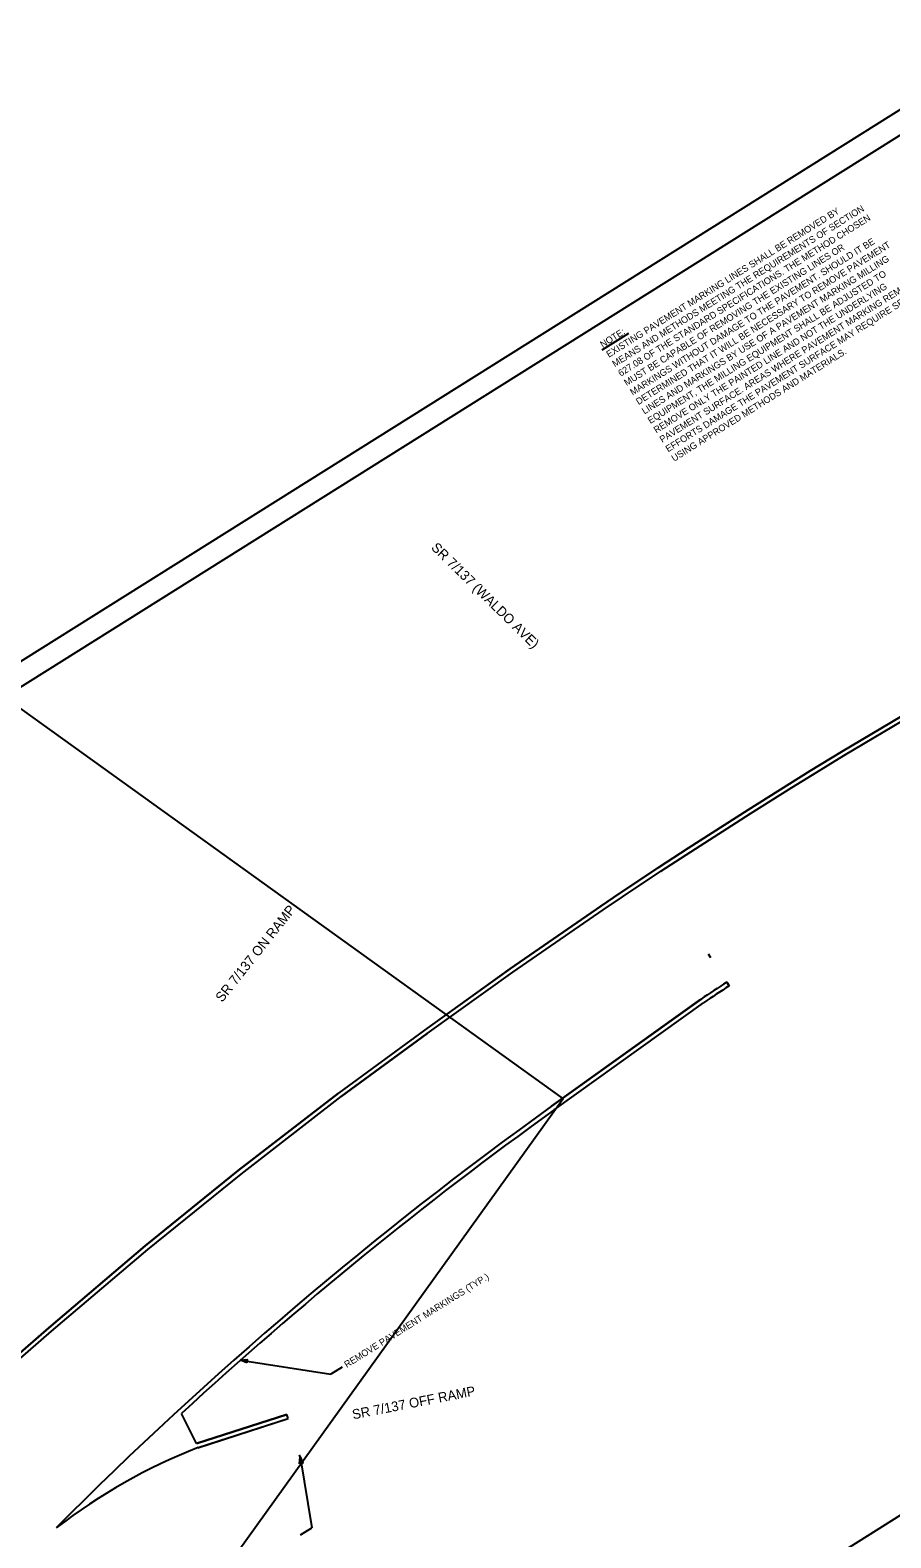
# Model space of a CAD drawing. Extents: x 1667656 to 1668829, y 338796 to 339856.
# Drawn here: x 1668089 to 1668476, y 339179 to 339856 of the extents above; entities that cross this region are included whole.
import ezdxf

# ---------------------------------------------------------------- set-up
doc = ezdxf.new("R2010")
doc.units = 0
for name, color, linetype in [('ANNOTATION', 7, 'Continuous'), ('BORDER', 7, 'Continuous'), ('CLIPS', 7, 'Continuous'), ('PATTERNING', 7, 'Continuous'), ('PLOT BOUNDARY', 7, 'Continuous'), ('SHADING', 7, 'Continuous')]:
    doc.layers.add(name, color=color, linetype=linetype)

msp = doc.modelspace()

# ---------------------------------------------------------------- linework, layer by layer
at = {"layer": 'ANNOTATION'}
for p, q in [((1668346.3, 339712.15), (1668358.23, 339719.63)), ((1668183.79, 339258.53), (1668224.46, 339252.32)), ((1668229.55, 339255.5), (1668224.46, 339252.32)), ((1668229.55, 339255.5), (1668224.46, 339252.32)), ((1668210.66, 339215.19), (1668215.82, 339183.28)), ((1668210.74, 339180.09), (1668215.82, 339183.28))]:
    msp.add_line(p, q, dxfattribs=at)
for points in [[(1668186.64, 339257.33), (1668183.79, 339258.53), (1668186.87, 339258.82)], [(1668210.4, 339212.11), (1668210.66, 339215.19), (1668211.88, 339212.35)]]:
    msp.add_lwpolyline(points, close=True, dxfattribs=at)
at = {"layer": 'BORDER'}
for p, q in [((1668534.13, 339842.47), (1667856.36, 339417.47)), ((1668135.26, 338972.68), (1668813.03, 339397.67))]:
    msp.add_line(p, q, dxfattribs=at)
at = {"layer": 'CLIPS'}
msp.add_lwpolyline([(1667655.9, 338980.65), (1668072.35, 339560.16), (1668328.75, 339375.91), (1667912.3, 338796.4)], close=True, dxfattribs=at)
at = {"layer": 'PATTERNING'}
for p, q in [((1668393.96, 339441), (1668395.06, 339439.32)), ((1668402.29, 339428.32), (1668403.38, 339426.65)), ((1668403.38, 339426.65), (1668402.29, 339428.32)), ((1668390.73, 339420.71), (1668323.63, 339372.6)), ((1668323.63, 339372.6), (1668390.7, 339420.69)), ((1668324.79, 339370.97), (1668391.87, 339419.07)), ((1668324.79, 339370.97), (1668391.84, 339419.05)), ((1668266.58, 339406.81), (1668227.92, 339378.52)), ((1668266.58, 339406.81), (1668227.92, 339378.52)), ((1668267.76, 339405.2), (1668229.1, 339376.91)), ((1668229.1, 339376.91), (1668267.76, 339405.2)), ((1668164.12, 339221.2), (1668157.32, 339234.63)), ((1668164.12, 339221.2), (1668157.32, 339234.63)), ((1668164.12, 339221.2), (1668204.61, 339234.26)), ((1668204.61, 339234.26), (1668164.12, 339221.2)), ((1668164.73, 339219.3), (1668205.21, 339232.35)), ((1668164.79, 339219.32), (1668205.21, 339232.35)), ((1668205.21, 339232.35), (1668204.61, 339234.26)), ((1668205.21, 339232.35), (1668204.61, 339234.26)), ((1668210.96, 339214.24), (1668210.36, 339216.14))]:
    msp.add_line(p, q, dxfattribs=at)
for points in [[(1668501.38, 339560.12), (1668485.21, 339550.34), (1668453.82, 339531.72), (1668439.78, 339523.17), (1668430.47, 339517.39), (1668411.93, 339505.7), (1668385.01, 339488.46), (1668371.6, 339479.76), (1668354.27, 339468.34), (1668345.7, 339462.5), (1668305.11, 339434.38), (1668266.58, 339406.81)], [(1668266.59, 339406.82), (1668305.11, 339434.38), (1668345.7, 339462.5), (1668354.27, 339468.34), (1668371.6, 339479.76), (1668385.01, 339488.46), (1668411.93, 339505.7), (1668430.47, 339517.39), (1668439.78, 339523.17), (1668453.82, 339531.72), (1668485.21, 339550.34), (1668501.38, 339560.12)], [(1668267.75, 339405.19), (1668306.26, 339432.75), (1668346.83, 339460.85), (1668355.39, 339466.68), (1668372.69, 339478.09), (1668386.09, 339486.78), (1668413, 339504.01), (1668431.53, 339515.69), (1668440.83, 339521.47), (1668454.85, 339530.01), (1668486.23, 339548.63), (1668502.42, 339558.41)], [(1668267.76, 339405.2), (1668306.26, 339432.75), (1668346.83, 339460.85), (1668355.39, 339466.68), (1668372.69, 339478.09), (1668386.09, 339486.78), (1668413, 339504.01), (1668431.53, 339515.69), (1668440.83, 339521.47), (1668454.85, 339530.01), (1668486.23, 339548.63), (1668502.42, 339558.41)], [(1668227.92, 339378.52), (1668182.86, 339343.68), (1668140.95, 339309.89), (1668097.67, 339273.13), (1668056.79, 339237.61), (1668017.96, 339202.04), (1668004.41, 339189.47)], [(1668004.41, 339189.47), (1668017.96, 339202.04), (1668056.79, 339237.61), (1668097.67, 339273.13), (1668140.95, 339309.89), (1668182.86, 339343.68), (1668227.9, 339378.51)], [(1668005.49, 339187.74), (1668019.32, 339200.57), (1668058.12, 339236.12), (1668098.97, 339271.61), (1668142.23, 339308.35), (1668184.1, 339342.11), (1668229.12, 339376.92)], [(1668005.49, 339187.74), (1668019.32, 339200.57), (1668058.12, 339236.12), (1668098.97, 339271.61), (1668142.23, 339308.35), (1668184.1, 339342.11), (1668229.1, 339376.91)]]:
    msp.add_lwpolyline(points, dxfattribs=at)
for centre, radius, start, end in [((1669833.32, 337242.02), 2613, 123.20653, 123.50984), ((1669833.32, 337242.02), 2613, 123.20653, 123.50984), ((1669833.32, 337242.02), 2611, 123.20646, 123.50984), ((1669833.32, 337242.02), 2611, 123.20646, 123.50984), ((1669352.68, 337937.4), 1766, 125.64099, 135.13115), ((1669352.68, 337937.4), 1766, 125.64099, 135.13115), ((1669352.68, 337937.4), 1764, 125.64099, 132.65968), ((1669352.68, 337937.4), 1764, 125.64099, 132.65968), ((1668259.16, 338978.13), 259, 111.36873, 127.61511), ((1668259.16, 338978.13), 259, 111.36873, 127.61511)]:
    msp.add_arc(centre, radius, start, end, dxfattribs=at)
at = {"layer": 'PLOT BOUNDARY'}
msp.add_lwpolyline([(1668109.1, 338938.23), (1668829.24, 339389.78), (1668537.05, 339855.75), (1667816.92, 339404.2)], close=True, dxfattribs=at)
at = {"layer": 'SHADING'}
for p, q in [((1668403.38, 339426.65), (1668402.29, 339428.32)), ((1668390.73, 339420.71), (1668323.63, 339372.6)), ((1668324.79, 339370.97), (1668391.84, 339419.05)), ((1668266.58, 339406.81), (1668227.92, 339378.52)), ((1668229.1, 339376.91), (1668267.76, 339405.2)), ((1668164.12, 339221.2), (1668157.32, 339234.63)), ((1668204.61, 339234.26), (1668164.12, 339221.2)), ((1668164.79, 339219.32), (1668205.21, 339232.35)), ((1668205.21, 339232.35), (1668204.61, 339234.26))]:
    msp.add_line(p, q, dxfattribs=at)
for points in [[(1668501.38, 339560.12), (1668485.21, 339550.34), (1668453.82, 339531.72), (1668439.78, 339523.17), (1668430.47, 339517.39), (1668411.93, 339505.7), (1668385.01, 339488.46), (1668371.6, 339479.76), (1668354.27, 339468.34), (1668345.7, 339462.5), (1668305.11, 339434.38), (1668266.58, 339406.81)], [(1668267.76, 339405.2), (1668306.26, 339432.75), (1668346.83, 339460.85), (1668355.39, 339466.68), (1668372.69, 339478.09), (1668386.09, 339486.78), (1668413, 339504.01), (1668431.53, 339515.69), (1668440.83, 339521.47), (1668454.85, 339530.01), (1668486.23, 339548.63), (1668502.42, 339558.41)], [(1668227.92, 339378.52), (1668182.86, 339343.68), (1668140.95, 339309.89), (1668097.67, 339273.13), (1668056.79, 339237.61), (1668017.96, 339202.04), (1668004.41, 339189.47)], [(1668005.49, 339187.74), (1668019.32, 339200.57), (1668058.12, 339236.12), (1668098.97, 339271.61), (1668142.23, 339308.35), (1668184.1, 339342.11), (1668229.1, 339376.91)]]:
    msp.add_lwpolyline(points, dxfattribs=at)
for centre, radius, start, end in [((1669833.32, 337242.02), 2613, 123.20653, 123.50984), ((1669833.32, 337242.02), 2611, 123.20646, 123.50984), ((1669352.68, 337937.4), 1766, 125.64099, 135.13115), ((1669352.68, 337937.4), 1764, 125.64099, 132.65968), ((1668259.16, 338978.13), 259, 111.36873, 127.61511)]:
    msp.add_arc(centre, radius, start, end, dxfattribs=at)

# ---------------------------------------------------------------- texts
at = {"layer": 'ANNOTATION'}
for s, height, rotation, p in [('MEANS AND METHODS MEETING THE REQUIREMENTS OF SECTION ', 3, 32.08927, (1668352, 339704.37)), ('EXISTING PAVEMENT MARKING LINES SHALL BE REMOVED BY ', 3, 32.08927, (1668349.34, 339708.62)), ('627.08 OF THE STANDARD SPECIFICATIONS. THE METHOD CHOSEN ', 3, 32.08927, (1668354.66, 339700.13)), ('MUST BE CAPABLE OF REMOVING THE EXISTING LINES OR ', 3, 32.08927, (1668357.33, 339695.88)), ('MARKINGS WITHOUT DAMAGE TO THE PAVEMENT. SHOULD IT BE ', 3, 32.08927, (1668359.99, 339691.64)), ('DETERMINED THAT IT WILL BE NECESSARY TO REMOVE PAVEMENT ', 3, 32.08927, (1668362.65, 339687.39)), ('LINES AND MARKINGS BY USE OF A PAVEMENT MARKING MILLING ', 3, 32.08927, (1668365.31, 339683.15)), ('EQUIPMENT, THE MILLING EQUIPMENT SHALL BE ADJUSTED TO ', 3, 32.08927, (1668367.97, 339678.9)), ('PAVEMENT SURFACE. AREAS WHERE PAVEMENT MARKING REMOVAL ', 3, 32.08927, (1668373.29, 339670.41)), ('REMOVE ONLY THE PAINTED LINE AND NOT THE UNDERLYING ', 3, 32.08927, (1668370.63, 339674.66)), ('EFFORTS DAMAGE THE PAVEMENT SURFACE MAY REQUIRE SEALING ', 3, 32.08927, (1668375.96, 339666.17)), ('NOTE:', 3, 32.08927, (1668346.56, 339713.05)), ('USING APPROVED METHODS AND MATERIALS.', 3, 32.08927, (1668378.62, 339661.92)), ('SR 7/137 (WALDO AVE)', 4.375, 315.57485, (1668269.2, 339623.05)), ('SR 7/137 ON RAMP', 4.375, 51.418, (1668175.61, 339419.01)), ('REMOVE PAVEMENT MARKINGS (TYP.)', 3, 32.08927, (1668231.61, 339255.03)), ('REMOVE PAVEMENT MARKINGS (TYP.)', 3, 32.08927, (1668231.61, 339255.03)), ('SR 7/137 OFF RAMP', 4.375, 11.04178, (1668234.48, 339231.99))]:
    msp.add_text(s, height=height, rotation=rotation, dxfattribs=at).set_placement(p)

doc.saveas('drawing.dxf')
